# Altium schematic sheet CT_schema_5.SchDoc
size 251 x 159 mm
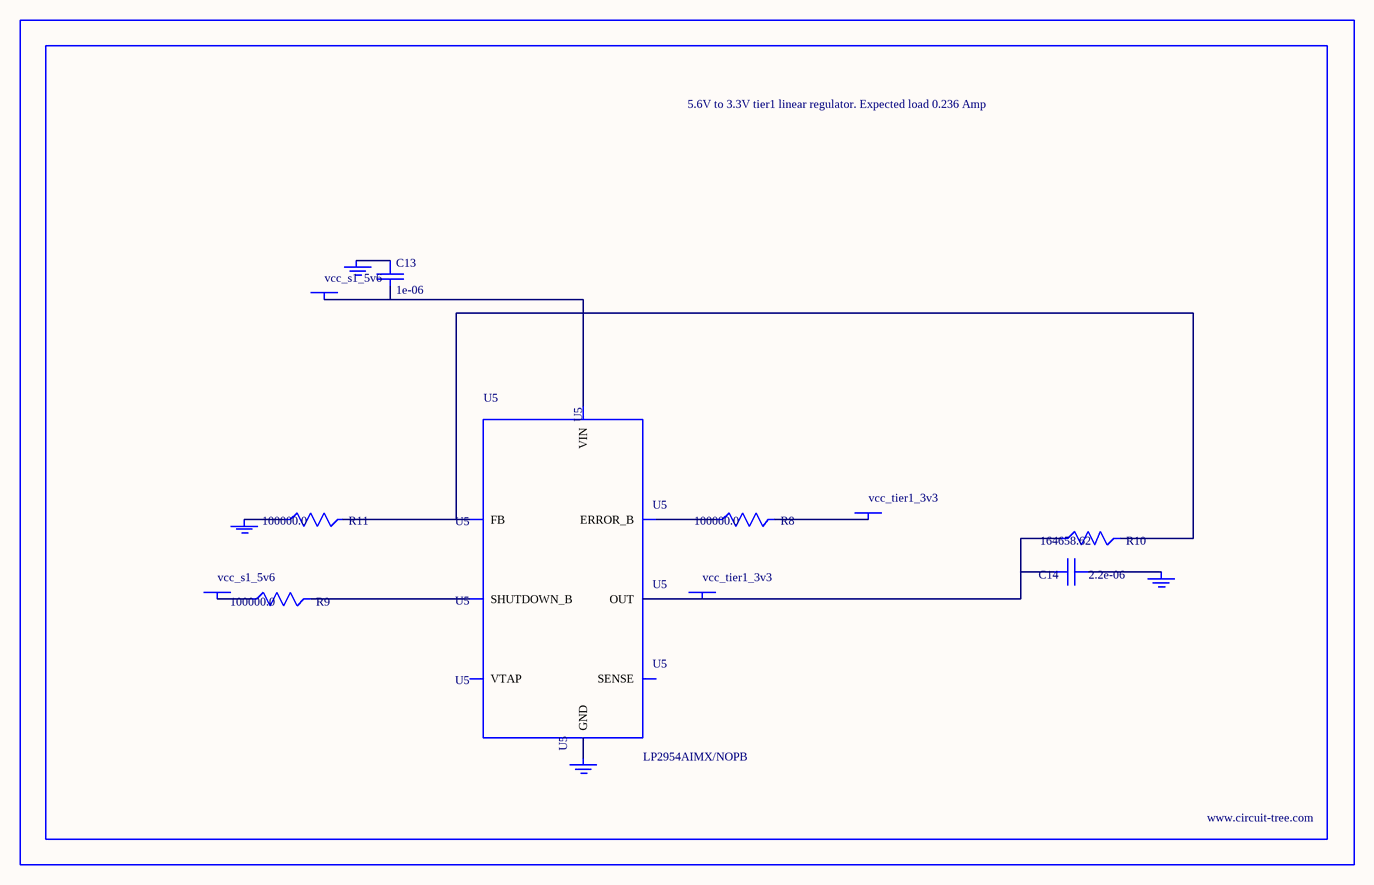
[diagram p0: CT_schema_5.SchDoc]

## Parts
BORDER4  (no value)
C13  1e-06  [EXV-9B]
C14  2.2e-06  [EXV-9B]
GND_INSTANCE_4_0  (no value)
GND_INSTANCE_4_1  (no value)
GND_INSTANCE_4_2  (no value)
GND_INSTANCE_4_3  (no value)
POWER_INSTANCE_4_0  vcc_s1_5v6
POWER_INSTANCE_4_1  vcc_tier1_3v3
POWER_INSTANCE_4_2  vcc_s1_5v6
POWER_INSTANCE_4_3  vcc_tier1_3v3
R8  100000.0  [R0603]
R9  100000.0  [R0603]
R10  164658.62  [R0603]
R11  100000.0  [R0603]
U5  LP2954AIMX/NOPB  [LP2954]

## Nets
NetC13_1: C13.1 GND_INSTANCE_4_2.0(GND)
NetC13_2: C13.2 POWER_INSTANCE_4_2.0(PWR) U5.8(VIN)
NetC14_1: C14.1 GND_INSTANCE_4_0.0(GND)
NetC14_2: C14.2 POWER_INSTANCE_4_3.0(PWR) R10.1 U5.1(OUT)
NetGND_INSTANCE_4_1_0: GND_INSTANCE_4_1.0(GND) R11.1
NetGND_INSTANCE_4_3_0: GND_INSTANCE_4_3.0(GND) U5.4(GND)
NetPOWER_INSTANCE_4_0_0: POWER_INSTANCE_4_0.0(PWR) R9.1
NetPOWER_INSTANCE_4_1_0: POWER_INSTANCE_4_1.0(PWR) R8.2
NetR8_1: R8.1 U5.5(ERROR_B)
NetR9_2: R9.2 U5.3(SHUTDOWN_B)
NetR10_2: R10.2 R11.2 U5.7(FB)

Not connected (* = marked no-connect by the designer): U5 2(SENSE) 6(VTAP)

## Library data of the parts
BORDER4 = BORDER_PAGE4
C13 = EDK105M050A9BAA
C14 = EDK225M050A9BAA
GND_INSTANCE_4_0-GND_INSTANCE_4_3 = GND
POWER_INSTANCE_4_0-POWER_INSTANCE_4_3 = PWR
R8 R9 R11 = RC0603JR-07100KL
R10 = R10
